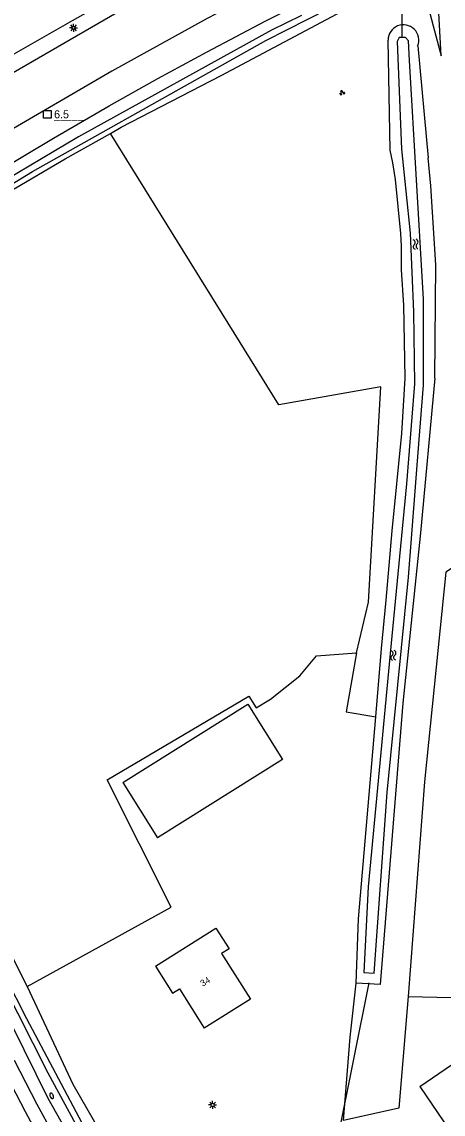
# Model space of a CAD drawing. Extents: x 133000 to 136000, y 400500 to 403500.
# Drawn here: x 133659.3 to 133725.1, y 400885.1 to 401055.6 of the extents above; entities that cross this region are included whole.
import ezdxf

# ---------------------------------------------------------------- set-up
doc = ezdxf.new("R2010")
doc.units = 0
for name, color, linetype in [('gg-afsc-draadraster', 7, 'Continuous'), ('gg-afsc-lijn draadraster', 7, 'Continuous'), ('gg-anno-huisnummerreeks BGT', 7, 'Continuous'), ('gg-bbg-bijgebouw', 7, 'Continuous'), ('gg-bbg-gedigitaliseerde bebouwing', 7, 'Continuous'), ('gg-bbg-gedigitaliseerde bijgebouw', 7, 'Continuous'), ('gg-bbg-hoofdgebouw', 7, 'Continuous'), ('gg-knt-BGT kruinlijn', 7, 'Continuous'), ('gg-knt-bovenkant onderkant talud', 7, 'Continuous'), ('gg-knt-bronhoudergrens', 7, 'Continuous'), ('gg-knt-verharding', 7, 'Continuous'), ('gg-knt-verharding nz', 7, 'Continuous'), ('gg-kntw-bovenkant insteek waterloop', 7, 'Continuous'), ('gg-kntw-waterlijn', 7, 'Continuous'), ('gg-kwrk-duiker nz buis', 7, 'Continuous'), ('gt-anno-nummer hm paal', 7, 'Continuous'), ('gt-grn-groengrens', 7, 'Continuous'), ('gt-symb-brandkraan', 7, 'Continuous'), ('gt-symb-groenvak', 7, 'Continuous'), ('gt-symb-hm paal', 7, 'Continuous'), ('gt-symb-lichtmast', 7, 'Continuous'), ('gt-symb-watersymbool', 7, 'Continuous')]:
    doc.layers.add(name, color=color, linetype=linetype)

# ---------------------------------------------------------------- blocks, each defined once
blk = doc.blocks.new('gt0-GRVAK')
at = {"layer": 'gt-symb-groenvak'}
for p, q in [((-0.11, 0.19), (-0.23, 0.24)), ((-0.18, 0.15), (0.09, 0.15)), ((-0.09, 0.21), (-0.16, 0.32)), ((-0.05, 0.21), (-0.05, 0.39)), ((0, 0.21), (0.06, 0.32)), ((0.01, 0.19), (0.13, 0.24)), ((0.26, -0.05), (0.2, 0.06)), ((0.3, -0.05), (0.3, 0.13)), ((0.35, -0.05), (0.41, 0.06)), ((-0.25, -0.23), (-0.36, -0.18)), ((-0.32, -0.26), (-0.05, -0.26)), ((-0.23, -0.21), (-0.29, -0.1)), ((-0.18, -0.2), (-0.18, -0.02)), ((-0.14, -0.21), (-0.07, -0.1)), ((-0.12, -0.23), (0, -0.18)), ((0.24, -0.07), (0.12, -0.02)), ((0.17, -0.11), (0.44, -0.11)), ((0.37, -0.07), (0.49, -0.02))]:
    blk.add_line(p, q, dxfattribs=at)
blk = doc.blocks.new('gt0-HMpaal')
at = {"layer": 'gt-symb-hm paal'}
blk.add_lwpolyline([(-0.6, 0.6), (0.6, 0.6), (0.6, -0.6), (-0.6, -0.6)], close=True, dxfattribs=at)
blk = doc.blocks.new('gt0-LMAST')
at = {"layer": 'gt-symb-lichtmast'}
for p, q in [((-0.18, 0.17), (-0.45, 0.44)), ((-0.01, 0.25), (-0.01, 0.62)), ((0.17, 0.17), (0.44, 0.44)), ((-0.26, 0), (-0.63, 0)), ((-0.18, -0.18), (-0.45, -0.45)), ((-0.01, -0.25), (-0.01, -0.63)), ((0.44, -0.45), (0.17, -0.18)), ((0.24, 0), (0.62, 0))]:
    blk.add_line(p, q, dxfattribs=at)
blk.add_circle((-0.01, 0), 0.25, dxfattribs=at)
blk = doc.blocks.new('gt0-WA')
at = {"layer": 'gt-symb-watersymbool'}
for centre, start, end in [((-0.32, 0.02), 28.0725, 151.9275), ((0.43, 0.42), 208.0725, 331.9275), ((-0.32, -0.43), 28.0725, 151.9275), ((0.43, -0.03), 208.0725, 331.9275)]:
    blk.add_arc(centre, 0.425, start, end, dxfattribs=at)
blk = doc.blocks.new('gt0-BR')
at = {"layer": 'gt-symb-brandkraan'}
for centre, radius, start, end in [((-0.24, 0), 0.206, 107.5669, 252.4331), ((0.6, -2.66), 3, 106.892, 107.5669), ((0, -0.69), 0.938, 73.108, 106.892), ((-0.6, -2.66), 3, 72.4331, 73.108), ((0.24, 0), 0.206, 287.567, 72.4331), ((0.6, 2.66), 3, 252.4331, 253.108), ((0, 0.69), 0.938, 253.108, 286.8921), ((-0.6, 2.66), 3, 286.8921, 287.567)]:
    blk.add_arc(centre, radius, start, end, dxfattribs=at)

msp = doc.modelspace()

# ---------------------------------------------------------------- linework, layer by layer
at = {"layer": 'gg-afsc-draadraster'}
for points in [[(133715.39, 400998.62), (133699.42, 400995.84), (133673.14, 401038.21)], [(133711.59, 400957.08), (133713.45, 400965.02), (133715.39, 400998.62)], [(133744.26, 400970.14), (133734.38, 400971.46), (133728.23, 400971.44), (133725.53, 400969.68), (133722.19, 400936.95), (133719.63, 400903.41)], [(133694.75, 400950.32), (133695.9, 400948.48), (133698.13, 400949.88), (133702.72, 400953.51), (133705.3, 400956.61), (133711.59, 400957.08)], [(133660.15, 400904.98), (133682.65, 400917.39), (133672.66, 400937.25)], [(133719.63, 400903.41), (133728.6, 400903.21), (133733.74, 400903.02), (133741.57, 400902.49), (133741.75, 400907.12)]]:
    msp.add_lwpolyline(points, dxfattribs=at)
at = {"layer": 'gg-afsc-lijn draadraster'}
for points in [[(133694.75, 400950.32), (133695.9, 400948.48), (133698.13, 400949.88), (133702.72, 400953.51), (133705.3, 400956.61), (133711.59, 400957.08)], [(133660.15, 400904.98), (133682.65, 400917.39), (133672.66, 400937.25)], [(133719.63, 400903.41), (133728.6, 400903.21), (133733.74, 400903.02), (133741.57, 400902.49), (133741.75, 400907.12)]]:
    msp.add_lwpolyline(points, dxfattribs=at)
at = {"layer": 'gg-bbg-bijgebouw'}
msp.add_line((133675.07, 400936.87), (133680.49, 400928.22), dxfattribs=at)
msp.add_lwpolyline([(133721.43, 400889.35), (133727.08, 400881.11), (133739.85, 400889.81)], dxfattribs=at)
at = {"layer": 'gg-bbg-gedigitaliseerde bebouwing'}
msp.add_line((133680.2, 400908.17), (133689.62, 400914.11), dxfattribs=at)
msp.add_lwpolyline([(133689.62, 400914.11), (133691.68, 400910.85), (133690.51, 400910.12), (133695.01, 400902.99), (133687.81, 400898.47)], dxfattribs=at)
at = {"layer": 'gg-bbg-gedigitaliseerde bijgebouw'}
for points in [[(133675.07, 400936.87), (133694.59, 400949.09), (133700.01, 400940.44), (133680.49, 400928.22)], [(133721.43, 400889.35), (133734.17, 400898.09), (133739.85, 400889.81)]]:
    msp.add_lwpolyline(points, dxfattribs=at)
at = {"layer": 'gg-bbg-hoofdgebouw'}
msp.add_lwpolyline([(133680.2, 400908.17), (133682.86, 400903.95), (133683.95, 400904.64), (133687.81, 400898.47)], dxfattribs=at)
at = {"layer": 'gg-knt-BGT kruinlijn'}
msp.add_lwpolyline([(133724.8, 401050.32), (133724.19, 401060.92), (133725.56, 401064.06), (133743.18, 401071.86), (133810.09, 401061.54)], dxfattribs=at)
at = {"layer": 'gg-knt-bovenkant onderkant talud'}
msp.add_lwpolyline([(133724.07, 401065.62), (133722.05, 401060.74), (133724.8, 401050.32)], dxfattribs=at)
at = {"layer": 'gg-knt-bronhoudergrens'}
msp.add_line((133672.66, 400937.25), (133694.75, 400950.32), dxfattribs=at)
at = {"layer": 'gg-knt-verharding'}
for points in [[(133813.12, 401111.85), (133795.39, 401105.32), (133777.17, 401098.12), (133759.95, 401090.8), (133743.01, 401083.28), (133729.12, 401076.72), (133705.11, 401064.96), (133688.26, 401056.14), (133673.39, 401047.95), (133655.48, 401037.51), (133647.05, 401032.42)], [(133600.99, 401015.72), (133607.35, 401019.68), (133631.11, 401034.41), (133643.95, 401042.23), (133655.96, 401049.39), (133667.23, 401055.85), (133681.15, 401063.71), (133693.35, 401070.58), (133695.94, 401072.05), (133704.47, 401077.25), (133718.91, 401086.13)], [(133721.24, 401081.4), (133699.67, 401070.65), (133674.14, 401057.03), (133652.62, 401044.62), (133624.63, 401027.52), (133602.29, 401013.66)], [(133658.12, 400893.46), (133661.67, 400886.59), (133666.58, 400877.67), (133669.28, 400872.89)]]:
    msp.add_lwpolyline(points, dxfattribs=at)
at = {"layer": 'gg-knt-verharding nz'}
msp.add_lwpolyline([(133656.18, 400892.48), (133659.83, 400885.48), (133664.62, 400876.53), (133667.39, 400871.76), (133670.91, 400865.82), (133675.34, 400858.79), (133675.26, 400858.74)], dxfattribs=at)
at = {"layer": 'gg-kntw-bovenkant insteek waterloop'}
for p, q in [((133716.84, 401035.6), (133716.5, 401052.78)), ((133721.12, 401051.88), (133722.73, 401034.39))]:
    msp.add_line(p, q, dxfattribs=at)
for points in [[(133610.45, 401000), (133610.34, 401002.54), (133612.12, 401005.73), (133633.87, 401018.75), (133649.14, 401028.32), (133655.68, 401032.34), (133664.28, 401037.46), (133672.93, 401042.49), (133680.55, 401046.79), (133688.23, 401050.97), (133697.3, 401055.73), (133706.43, 401060.37), (133707.98, 401061.05), (133711.7, 401062.52), (133713.36, 401059.62)], [(133673.14, 401038.21), (133674.82, 401039.16), (133690.45, 401047.26), (133708.55, 401056.87), (133713.36, 401059.62)], [(133614.49, 401000), (133614.42, 401000.87), (133616.2, 401003.05), (133623.1, 401007.9), (133635.5, 401015.81), (133639.76, 401018.46), (133648.61, 401023.86), (133657.48, 401029.19), (133666.11, 401034.24), (133673.14, 401038.21)], [(133719.16, 401000), (133718.94, 401011.37), (133718.61, 401016.91), (133718.6, 401020.61), (133718.51, 401022.6), (133717.66, 401031.03), (133717.26, 401033.64), (133716.84, 401035.6)], [(133723.78, 401000), (133723.94, 401017.67), (133723.18, 401030), (133722.73, 401034.39)], [(133723.78, 401000), (133721.57, 400975.85), (133718.82, 400949.23), (133715.25, 400905.28), (133711.52, 400905.49)], [(133716.18, 400965.3), (133717.16, 400976.13), (133718.64, 400991.35), (133719.16, 401000)], [(133714.58, 400947.08), (133715.49, 400957.78), (133716.18, 400965.3)], [(133711.52, 400905.49), (133711.89, 400915.58), (133714.58, 400947.08)], [(133647.32, 400922.51), (133651.05, 400912.57), (133655.81, 400902.73), (133663.36, 400887.54), (133670.14, 400875.56)], [(133653.19, 400919.29), (133655.28, 400914.54), (133660.15, 400904.98)], [(133660.15, 400904.98), (133667.27, 400889.72), (133673.84, 400878.31), (133674.12, 400877.9), (133674.32, 400877.44)]]:
    msp.add_lwpolyline(points, dxfattribs=at)
msp.add_arc((133718.9, 401052.78), 2.39, 337.9384, 179.8817, dxfattribs=at)
at = {"layer": 'gg-kntw-waterlijn'}
for points in [[(133669.18, 400882.87), (133660.12, 400899.95), (133656.82, 400906.41), (133654.57, 400911.05), (133649.82, 400922.13), (133646.2, 400931.35), (133641.05, 400943.09), (133637.2, 400950.93), (133633.96, 400956.69), (133623.05, 400975.36), (133620.28, 400980.93), (133615.75, 400992.22), (133613.24, 400998.75), (133612.98, 400999.88), (133612.87, 401000.91), (133613.8, 401002.48), (133615.03, 401003.82), (133616.52, 401004.87), (133629.87, 401013.24), (133660.98, 401032.24), (133689.36, 401048.21), (133697.39, 401052.73), (133707.23, 401057.72)], [(133702.99, 401056.63), (133698.28, 401054.31), (133668.17, 401037.68), (133654.64, 401029.65), (133630.29, 401014.66), (133622.46, 401009.84), (133613.63, 401004.19), (133612.9, 401003.4), (133612.11, 401002.06), (133611.98, 401000.71), (133612.11, 400998.67), (133615.82, 400989.68), (133618.37, 400982.88), (133621.83, 400975.78), (133627.74, 400965.27), (133636.2, 400950.54), (133640.67, 400941.17), (133648.67, 400922.77), (133653.89, 400910.16), (133663.36, 400891.53), (133670.02, 400879.23)], [(133717.94, 401052.54), (133718.59, 401035.77), (133719.92, 401022.65), (133720.47, 401010.34), (133720.63, 400999.08), (133719.35, 400983.5), (133716.84, 400957.01), (133713.38, 400920.54), (133712.7, 400907.15), (133714.31, 400907.07), (133716.36, 400935.29), (133719.66, 400968.89), (133721.36, 400990.43), (133722.04, 400998.89), (133722.04, 401012.32), (133719.83, 401049.57), (133719.66, 401052.65), (133719.22, 401053.21), (133718.25, 401053.21), (133717.94, 401052.54)]]:
    msp.add_lwpolyline(points, dxfattribs=at)
at = {"layer": 'gg-kwrk-duiker nz buis'}
for points in [[(133718.7, 401053.31), (133719, 401101), (133723.12, 401113.14)], [(133698.9, 400831.32), (133699, 400833), (133713.54, 400905.54)]]:
    msp.add_lwpolyline(points, dxfattribs=at)
at = {"layer": 'gt-grn-groengrens'}
for points in [[(133711.59, 400957.08), (133709.98, 400947.89), (133714.58, 400947.08)], [(133719.63, 400903.41), (133718.16, 400886), (133709.53, 400884.07), (133710.59, 400897.1), (133711.52, 400905.49)]]:
    msp.add_lwpolyline(points, dxfattribs=at)

# ---------------------------------------------------------------- block references
at = {"layer": 'gt-symb-brandkraan', "rotation": 113.13090948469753}
msp.add_blockref('gt0-BR', (133663.98, 400887.9), dxfattribs=at)
at = {"layer": 'gt-symb-groenvak'}
msp.add_blockref('gt0-GRVAK', (133709.32, 401044.57), dxfattribs=at)
at = {"layer": 'gt-symb-hm paal'}
msp.add_blockref('gt0-HMpaal', (133663.28, 401041.17), dxfattribs=at)
at = {"layer": 'gt-symb-lichtmast'}
for p in [(133667.4, 401054.7), (133689.11, 400886.5)]:
    msp.add_blockref('gt0-LMAST', p, dxfattribs=at)
at = {"layer": 'gt-symb-watersymbool'}
for p, rotation in [((133720.79, 401020.96), -78.81367070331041), ((133717.32, 400956.64), 97.64386978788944)]:
    msp.add_blockref('gt0-WA', p, dxfattribs=dict(at, rotation=rotation))

# ---------------------------------------------------------------- texts
at = {"layer": 'gg-anno-huisnummerreeks BGT'}
msp.add_text('34', height=1, rotation=32, dxfattribs=at).set_placement((133687.57, 400904.94))
at = {"layer": 'gt-anno-nummer hm paal'}
msp.add_text('6.5', height=1.25, dxfattribs=at).set_placement((133664.36, 401040.57))
at = {"layer": 'gt-symb-hm paal'}
msp.add_text('_____', height=1.25, dxfattribs=at).set_placement((133664.36, 401040.57))

doc.saveas('drawing.dxf')
